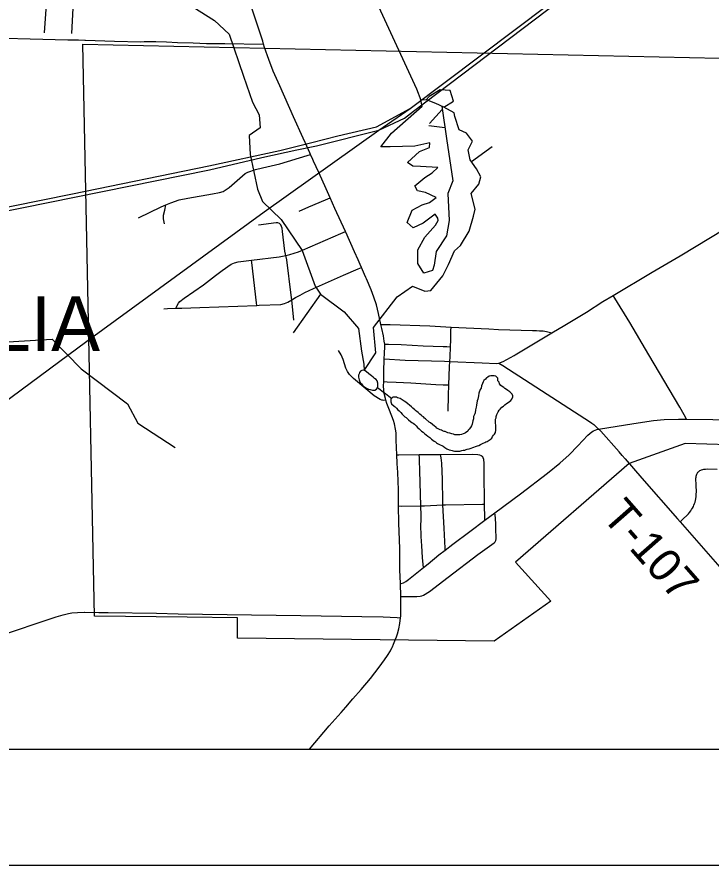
# Model space of a CAD drawing. Extents: x 0 to 34, y 0 to 22.
# Drawn here: x 6.712 to 7.312, y 14 to 14.733 of the extents above; entities that cross this region are included whole.
import ezdxf

# ---------------------------------------------------------------- set-up
doc = ezdxf.new("R2010")
doc.units = 0
for name, color, linetype in [('GM_X_City_Street', 7, 'Continuous'), ('GM_X_Corporation', 7, 'Continuous'), ('GM_X_Corporation_Text', 7, 'Continuous'), ('GM_X_County_Road', 7, 'Continuous'), ('GM_X_Minor_Lake', 7, 'Continuous'), ('GM_X_Minor_River', 7, 'Continuous'), ('GM_X_Rail_Line', 7, 'Continuous'), ('GM_X_State_Route', 7, 'Continuous'), ('GM_X_Township_Road', 7, 'Continuous'), ('GM_X_Township_Road_Text', 7, 'Continuous'), ('SH_Data', 7, 'Continuous')]:
    doc.layers.add(name, color=color, linetype=linetype)

msp = doc.modelspace()

# ---------------------------------------------------------------- linework, layer by layer
at = {"layer": 'GM_X_City_Street'}
for points in [[(6.81731, 14.55908), (6.8371, 14.56867), (6.84094, 14.57031), (6.8454, 14.57222), (6.85255, 14.57456), (6.86005, 14.57624), (6.88142, 14.57977), (6.88755, 14.5809), (6.89051, 14.58202), (6.89323, 14.58354), (6.89579, 14.58535), (6.90976, 14.59741), (6.91187, 14.59858), (6.91849, 14.60097), (6.92451, 14.60231), (6.93956, 14.60592), (6.9631, 14.61288), (6.96622, 14.6138)], [(6.95625, 14.56495), (6.96453, 14.56858), (6.97917, 14.57476), (6.983, 14.57648)], [(6.83993, 14.55384), (6.83914, 14.55836), (6.83917, 14.56132), (6.84006, 14.56581), (6.84094, 14.57031)], [(6.94471, 14.52657), (6.94441, 14.52772), (6.94392, 14.53034), (6.94192, 14.54734), (6.94147, 14.55024), (6.94108, 14.55171), (6.94038, 14.55308), (6.9393, 14.55415), (6.93791, 14.55477), (6.93639, 14.55477), (6.92117, 14.55279)], [(6.84965, 14.48105), (6.85058, 14.48277), (6.85209, 14.48555), (6.85315, 14.48677), (6.85681, 14.48975), (6.87359, 14.50124), (6.88411, 14.50936), (6.88964, 14.5137), (6.89748, 14.519), (6.90036, 14.52037), (6.90346, 14.52112), (6.91507, 14.52254), (6.93898, 14.52547), (6.94471, 14.52657), (6.94828, 14.52747), (6.95583, 14.52988), (6.95928, 14.5312), (6.99244, 14.54572), (6.99645, 14.54748)], [(6.91982, 14.48351), (6.91955, 14.48577), (6.91531, 14.52051), (6.91507, 14.52254)], [(6.9517, 14.47073), (6.94986, 14.48837), (6.94945, 14.4923), (6.94566, 14.5229), (6.94508, 14.52539), (6.94471, 14.52657)], [(6.83946, 14.4806), (6.84254, 14.48084), (6.84965, 14.48105), (6.85492, 14.4812), (6.87048, 14.4818), (6.91982, 14.48351), (6.92175, 14.48357), (6.94042, 14.48439), (6.94356, 14.485), (6.94651, 14.48624), (6.94986, 14.48837), (6.95312, 14.49045), (6.95702, 14.49242), (6.96133, 14.49457), (6.96882, 14.49808), (6.99464, 14.50966), (7.00721, 14.51512), (7.01008, 14.51636)], [(7.29116, 14.38519), (7.2891, 14.38893), (7.28537, 14.39568), (7.25852, 14.44082), (7.24219, 14.46878), (7.22907, 14.48973), (7.22762, 14.49203)], [(7.02683, 14.46707), (7.0302, 14.46698), (7.03488, 14.46686), (7.06911, 14.46587), (7.08762, 14.46466), (7.12016, 14.46314), (7.12862, 14.46275), (7.15795, 14.4618), (7.16149, 14.46175), (7.16411, 14.46165), (7.1671, 14.46142), (7.17005, 14.46082), (7.17479, 14.45986)], [(7.08654, 14.43517), (7.08669, 14.43916), (7.08701, 14.44764), (7.08723, 14.45367), (7.08751, 14.46155), (7.08762, 14.46466)], [(7.0302, 14.45012), (7.03351, 14.45001), (7.04449, 14.44963), (7.06335, 14.44862), (7.08064, 14.4481), (7.08378, 14.44788), (7.08701, 14.44764)], [(7.03127, 14.40149), (7.03081, 14.40152), (7.02953, 14.40137), (7.02839, 14.40152), (7.0276, 14.40173), (7.02632, 14.4023), (7.02121, 14.4055), (7.01391, 14.41133), (7.00319, 14.42036), (6.99993, 14.42379), (6.99809, 14.42638), (6.9967, 14.42924), (6.99433, 14.43666), (6.99253, 14.44072), (6.99027, 14.44458)], [(7.08516, 14.39201), (7.08539, 14.40575), (7.08575, 14.41491), (7.08636, 14.43051), (7.08654, 14.43517)], [(7.02935, 14.4177), (7.03242, 14.41754), (7.04022, 14.41713), (7.05273, 14.41669), (7.0745, 14.41507), (7.08074, 14.41498), (7.08575, 14.41491)], [(7.04374, 14.24309), (7.04456, 14.24328), (7.04652, 14.24374), (7.04853, 14.24501), (7.05087, 14.24662), (7.06385, 14.25709), (7.06773, 14.26022), (7.07708, 14.26793), (7.08255, 14.27217), (7.08897, 14.27715), (7.10366, 14.28827), (7.11687, 14.29803), (7.12548, 14.30439), (7.14765, 14.32078), (7.17103, 14.33849), (7.18167, 14.34725), (7.18968, 14.3545), (7.19727, 14.36224), (7.20566, 14.37136), (7.20925, 14.3744), (7.21056, 14.37522), (7.21349, 14.37629), (7.21511, 14.37655)], [(7.23808, 14.35089), (7.23554, 14.35378), (7.23276, 14.35692), (7.21707, 14.3747), (7.21613, 14.37562), (7.21511, 14.37655)], [(7.04063, 14.35442), (7.04241, 14.35444), (7.05994, 14.3546), (7.07852, 14.35472), (7.10598, 14.3549), (7.11063, 14.35462), (7.11221, 14.35435), (7.11348, 14.35387), (7.11457, 14.35317)], [(7.06385, 14.25709), (7.06355, 14.25951), (7.06277, 14.26561), (7.0624, 14.27586), (7.06176, 14.2839), (7.06156, 14.29412), (7.06172, 14.29745), (7.06159, 14.30209), (7.06136, 14.31035), (7.06053, 14.34054), (7.06036, 14.34985), (7.06023, 14.35139), (7.05994, 14.3546)], [(7.08255, 14.27217), (7.08246, 14.27378), (7.08154, 14.29101), (7.08054, 14.31115), (7.08039, 14.31421), (7.08018, 14.33301), (7.07951, 14.3471), (7.0789, 14.3518), (7.07852, 14.35472)], [(7.11687, 14.29803), (7.11676, 14.30163), (7.11651, 14.30942), (7.11649, 14.31032), (7.11643, 14.31185), (7.11624, 14.33936), (7.11623, 14.34708), (7.11591, 14.35025), (7.11545, 14.35179), (7.1149, 14.35265), (7.11457, 14.35317)], [(7.04216, 14.31019), (7.04442, 14.31018), (7.06136, 14.31035), (7.06295, 14.31032), (7.06451, 14.31029), (7.08054, 14.31115), (7.08272, 14.31119), (7.11481, 14.31182), (7.11643, 14.31185)], [(7.04405, 14.23186), (7.04702, 14.23204), (7.04856, 14.23214), (7.05787, 14.23208), (7.06096, 14.23227), (7.06244, 14.23266), (7.06384, 14.23325), (7.06905, 14.23646), (7.08496, 14.24866), (7.11082, 14.26836), (7.12473, 14.27823), (7.12578, 14.27936), (7.12637, 14.28036), (7.12658, 14.28176), (7.12652, 14.28439), (7.12638, 14.28831), (7.12632, 14.29386), (7.12608, 14.30005), (7.12548, 14.30439)]]:
    msp.add_lwpolyline(points, dxfattribs=at)
at = {"layer": 'GM_X_Corporation'}
msp.add_lwpolyline([(6.7693, 14.70911), (7.34604, 14.69664), (7.34606, 14.56029), (7.34608, 14.36247), (7.29001, 14.36406), (7.24163, 14.34695), (7.14334, 14.26178), (7.17374, 14.22784), (7.12479, 14.19331), (6.90309, 14.19603), (6.90294, 14.21358), (6.85937, 14.21402), (6.77953, 14.215), (6.7728, 14.54029)], close=True, dxfattribs=at)
for points in [[(6.0392, 14.6694), (6.04124, 14.60572), (6.04279, 14.55293), (6.04563, 14.45974), (6.04662, 14.41624), (6.04684, 14.41003), (6.04687, 14.40695), (6.04749, 14.3899), (6.04788, 14.37904), (6.05092, 14.27972), (6.05218, 14.24245), (6.05455, 14.1679), (6.05638, 14.11355), (6.05687, 14.1), (8.9, 14.1)], [(6.0392, 14.6694), (6.04124, 14.60572), (6.04279, 14.55293), (6.04563, 14.45974), (6.04662, 14.41624), (6.04684, 14.41003), (6.04687, 14.40695), (6.04749, 14.3899), (6.04788, 14.37904), (6.05092, 14.27972), (6.05218, 14.24245), (6.05455, 14.1679), (6.05638, 14.11355), (6.05687, 14.1), (8.65472, 14.1)]]:
    msp.add_lwpolyline(points, dxfattribs=at)
at = {"layer": 'GM_X_County_Road'}
for points in [[(7.12893, 14.4337), (7.13224, 14.43156), (7.18449, 14.39783), (7.20812, 14.38254), (7.20913, 14.38185), (7.21097, 14.38051), (7.21276, 14.37886), (7.21511, 14.37655)], [(7.21511, 14.37655), (7.24563, 14.38154), (7.26252, 14.38407), (7.27181, 14.38498), (7.28425, 14.38531), (7.29116, 14.38519)], [(7.29116, 14.38519), (7.31375, 14.38481), (7.34655, 14.38368)]]:
    msp.add_lwpolyline(points, dxfattribs=at)
at = {"layer": 'GM_X_Minor_Lake'}
for points in [[(7.01433, 14.42634), (7.01281, 14.42711), (7.01148, 14.4275), (7.01034, 14.42713), (7.00939, 14.42676), (7.00843, 14.42563), (7.00804, 14.42449), (7.00765, 14.42316), (7.00763, 14.42145), (7.00782, 14.4203), (7.00819, 14.41916), (7.00856, 14.41821), (7.00912, 14.41687), (7.01006, 14.41572), (7.01138, 14.414), (7.01271, 14.41304), (7.01384, 14.41227), (7.01498, 14.41169)], [(7.01433, 14.42634), (7.01281, 14.42711), (7.01148, 14.4275), (7.01034, 14.42713), (7.00939, 14.42676), (7.00843, 14.42563), (7.00804, 14.42449), (7.00765, 14.42316), (7.00763, 14.42145), (7.00782, 14.4203), (7.00819, 14.41916), (7.00856, 14.41821), (7.00912, 14.41687), (7.01006, 14.41572), (7.01138, 14.414), (7.01271, 14.41304), (7.01384, 14.41227), (7.01498, 14.41169), (7.01631, 14.41111), (7.01764, 14.41072), (7.01953, 14.41033), (7.02087, 14.41032), (7.02182, 14.41031), (7.02315, 14.41106), (7.02392, 14.41238), (7.02432, 14.41371), (7.02432, 14.41466), (7.02434, 14.41638), (7.02359, 14.41828), (7.02284, 14.41943), (7.02151, 14.42039), (7.02019, 14.42135), (7.01886, 14.4225), (7.01773, 14.42346), (7.01659, 14.42423), (7.01433, 14.42634)], [(7.01498, 14.41169), (7.01631, 14.41111), (7.01764, 14.41072), (7.01953, 14.41033), (7.02087, 14.41032), (7.02182, 14.41031), (7.02315, 14.41106), (7.02392, 14.41238), (7.02432, 14.41371), (7.02432, 14.41466), (7.02434, 14.41638), (7.02359, 14.41828), (7.02284, 14.41943), (7.02151, 14.42039), (7.02019, 14.42135), (7.01886, 14.4225), (7.01773, 14.42346), (7.01659, 14.42423), (7.01433, 14.42634)], [(7.14006, 14.40237), (7.14103, 14.40445), (7.14085, 14.40541), (7.14029, 14.40674), (7.13934, 14.40808), (7.1384, 14.40885), (7.13745, 14.40943), (7.13651, 14.41), (7.13537, 14.41077), (7.13405, 14.41173), (7.1331, 14.4125), (7.13178, 14.41346), (7.13045, 14.41442), (7.12951, 14.41576), (7.12914, 14.4171), (7.12801, 14.41844), (7.12803, 14.42072), (7.12614, 14.42245), (7.12481, 14.42264), (7.12348, 14.42266), (7.12196, 14.42267), (7.12062, 14.4223), (7.11928, 14.42155), (7.11814, 14.42079), (7.11737, 14.41966), (7.11603, 14.41853), (7.11526, 14.41739), (7.11468, 14.41607), (7.1139, 14.41398), (7.11351, 14.41208), (7.11274, 14.41075), (7.11157, 14.40772), (7.11117, 14.40525), (7.11077, 14.40259), (7.11019, 14.40108), (7.10959, 14.39728), (7.1092, 14.39557), (7.1088, 14.39329), (7.1084, 14.39063), (7.10802, 14.38968), (7.10705, 14.3876), (7.10684, 14.38551), (7.10626, 14.3838), (7.10567, 14.38095), (7.10509, 14.37943), (7.10431, 14.37792), (7.10335, 14.37659), (7.1024, 14.37584), (7.10201, 14.37489), (7.10009, 14.37339), (7.09895, 14.37282), (7.098, 14.37245), (7.09647, 14.37208), (7.09514, 14.37171), (7.094, 14.37153), (7.09266, 14.37154), (7.09171, 14.37155), (7.09076, 14.37175), (7.08962, 14.37213), (7.08811, 14.37253), (7.0864, 14.37311), (7.08488, 14.3735), (7.08374, 14.37408), (7.08261, 14.37447), (7.08166, 14.37467), (7.08014, 14.37525), (7.07919, 14.37564), (7.07824, 14.37602), (7.07654, 14.37699), (7.0754, 14.37757), (7.07427, 14.37853), (7.07332, 14.3793), (7.07143, 14.38064), (7.06973, 14.38198), (7.06878, 14.38256), (7.06557, 14.38544), (7.06462, 14.38621), (7.06368, 14.38717), (7.06273, 14.38793), (7.06179, 14.3887), (7.06047, 14.38966), (7.05914, 14.391), (7.05801, 14.39177), (7.05706, 14.39254), (7.05612, 14.39331), (7.05461, 14.39465), (7.05328, 14.3958), (7.05158, 14.39734), (7.05007, 14.39849), (7.04837, 14.39984), (7.04704, 14.4008), (7.04534, 14.40195), (7.04439, 14.40253), (7.04345, 14.40311), (7.0425, 14.40349), (7.04136, 14.40369), (7.04041, 14.40408), (7.03889, 14.40428), (7.03737, 14.40429), (7.03618, 14.40312)], [(7.03618, 14.40312), (7.03564, 14.4026), (7.03544, 14.40108), (7.03561, 14.40021), (7.03599, 14.39841), (7.03826, 14.39649), (7.03921, 14.39572), (7.04034, 14.39457), (7.04166, 14.39323), (7.0428, 14.39227), (7.04412, 14.39093), (7.04544, 14.38959), (7.04657, 14.38825), (7.0477, 14.38729), (7.04865, 14.38652), (7.04997, 14.38556), (7.05092, 14.3846), (7.05262, 14.38307), (7.05375, 14.3823), (7.0547, 14.38172), (7.05583, 14.38076), (7.05734, 14.37942), (7.05867, 14.37808), (7.05999, 14.37693), (7.06112, 14.37577), (7.06207, 14.37482), (7.06358, 14.37404), (7.06471, 14.37289), (7.06604, 14.37174), (7.06755, 14.37059), (7.06925, 14.36925), (7.07076, 14.3679), (7.0719, 14.36694), (7.07284, 14.36618), (7.07398, 14.3656), (7.07492, 14.36483), (7.07587, 14.36425), (7.07814, 14.3629), (7.07966, 14.36232), (7.08061, 14.36174), (7.08231, 14.36059), (7.08402, 14.35962), (7.08591, 14.35885), (7.08724, 14.35846), (7.08838, 14.35807), (7.08952, 14.35787), (7.09066, 14.35767), (7.09199, 14.35747), (7.09313, 14.35746), (7.09408, 14.35746), (7.09522, 14.35764), (7.09694, 14.358), (7.09808, 14.35838), (7.09941, 14.35856), (7.10056, 14.35893), (7.10151, 14.3593), (7.10323, 14.35967), (7.10494, 14.36023), (7.10628, 14.3606), (7.10723, 14.36097), (7.10876, 14.36153), (7.11028, 14.36209), (7.11162, 14.36246), (7.11295, 14.36321), (7.1141, 14.36377), (7.11524, 14.36433), (7.11677, 14.36508), (7.11773, 14.36564), (7.11868, 14.36602), (7.12136, 14.36771), (7.1227, 14.36884), (7.12347, 14.37016), (7.12423, 14.3713), (7.125, 14.37224), (7.12596, 14.37357), (7.12636, 14.37566), (7.12637, 14.37661), (7.12637, 14.37756), (7.12639, 14.37908), (7.1262, 14.38003), (7.12603, 14.38175), (7.12603, 14.38308), (7.12604, 14.38403), (7.12605, 14.38517), (7.12644, 14.38631), (7.12645, 14.38764), (7.12703, 14.38916), (7.12761, 14.39029), (7.12838, 14.39162), (7.12915, 14.39294), (7.12992, 14.39389), (7.13145, 14.39559), (7.13279, 14.39653), (7.13413, 14.39766), (7.13547, 14.3986), (7.137, 14.39954), (7.13929, 14.40123), (7.14006, 14.40237)]]:
    msp.add_lwpolyline(points, dxfattribs=at)
at = {"layer": 'GM_X_Minor_River'}
for points in [[(6.96298, 14.87618), (7.0578, 14.67059), (7.06134, 14.66086)], [(6.73634, 14.71907), (6.74145, 14.79206), (6.74647, 14.8021), (6.74728, 14.80951)], [(6.75992, 14.71851), (6.76238, 14.76756), (6.76854, 14.77778), (6.76956, 14.78652)], [(6.86451, 14.74148), (6.88307, 14.72974), (6.89572, 14.71785), (6.90819, 14.68143), (6.91602, 14.65912), (6.92164, 14.64824), (6.92251, 14.63701), (6.91295, 14.63023), (6.91397, 14.61387), (6.92021, 14.58377), (6.92451, 14.57328), (6.94075, 14.55775), (6.95881, 14.5308)], [(7.08135, 14.65486), (7.08968, 14.65989), (7.08689, 14.66904), (7.07815, 14.66986), (7.06859, 14.66385), (7.06608, 14.66101)], [(7.01234, 14.42725), (7.02263, 14.44244), (7.02051, 14.46452), (7.04106, 14.49099), (7.05425, 14.50002), (7.06487, 14.49575), (7.07001, 14.49629), (7.08056, 14.50895), (7.08539, 14.5188), (7.09062, 14.53055), (7.09579, 14.53527), (7.1033, 14.54776), (7.10701, 14.56067), (7.10838, 14.56655), (7.10487, 14.58008), (7.11159, 14.58821), (7.11335, 14.59447), (7.10959, 14.60135), (7.10413, 14.60919), (7.10249, 14.61795), (7.10616, 14.62534), (7.10088, 14.63241), (7.09463, 14.63512), (7.09072, 14.64657), (7.09017, 14.6498), (7.08146, 14.65481), (7.07445, 14.65791), (7.06629, 14.66102), (7.06134, 14.66086)], [(7.07945, 14.6557), (7.08354, 14.6276), (7.08916, 14.59104), (7.08471, 14.58005), (7.08587, 14.55683), (7.08349, 14.54373), (7.07463, 14.5301), (7.07303, 14.51832), (7.07147, 14.51358), (7.06403, 14.51136), (7.05896, 14.51976), (7.05886, 14.53156), (7.06503, 14.54235), (7.07404, 14.55293), (7.07636, 14.55672), (7.07618, 14.559), (7.07373, 14.56244), (7.06359, 14.55453), (7.05482, 14.55061), (7.04971, 14.55502), (7.05398, 14.56564), (7.06257, 14.57032), (7.06905, 14.57237), (7.0746, 14.5767), (7.0655, 14.58114), (7.05848, 14.58234), (7.05623, 14.58692), (7.06484, 14.59389), (7.07134, 14.59803), (7.07613, 14.60255), (7.06111, 14.60343), (7.05464, 14.60367), (7.04991, 14.60694), (7.06025, 14.61656), (7.06884, 14.61992), (7.06925, 14.62391), (7.05629, 14.62096), (7.0348, 14.62056), (7.027, 14.62062), (7.03602, 14.63215), (7.06264, 14.65553), (7.06134, 14.66086)], [(7.07987, 14.65283), (7.0688, 14.64065)], [(7.08219, 14.63689), (7.06822, 14.63875)], [(7.10509, 14.60781), (7.12305, 14.62083)], [(6.95881, 14.5308), (6.97018, 14.50009), (6.97469, 14.49321), (6.99512, 14.47784), (7.00757, 14.46367), (7.01009, 14.44406), (7.01209, 14.43282), (7.01234, 14.42725)], [(6.97469, 14.49321), (6.95124, 14.45972)], [(6.60402, 14.446), (6.74274, 14.45428), (6.76785, 14.42879), (6.80794, 14.39844), (6.81695, 14.38163), (6.84913, 14.36066)], [(7.03618, 14.40312), (7.02393, 14.41241)]]:
    msp.add_lwpolyline(points, dxfattribs=at)
at = {"layer": 'GM_X_Rail_Line'}
msp.add_line((7.02524, 14.63495), (7.05235, 14.65372), dxfattribs=at)
for points in [[(7.02524, 14.63495), (7.04728, 14.64538), (7.05504, 14.65131), (7.2329, 14.78614), (7.45402, 14.95299), (7.62987, 15.08397), (7.90392, 15.28739), (8.1825, 15.49291), (8.39874, 15.65453), (8.55126, 15.76844)], [(7.05235, 14.65372), (7.23255, 14.78962), (7.44775, 14.9523), (7.50799, 14.99688), (7.62848, 15.0864), (7.90044, 15.28913), (8.18737, 15.50057), (8.39561, 15.65662), (8.55056, 15.77192)], [(6.04866, 14.43974), (6.33792, 14.49548), (6.6004, 14.54763), (6.76038, 14.57982), (6.87836, 14.60396), (6.93973, 14.61737), (6.96714, 14.62422), (6.98978, 14.62988), (7.02315, 14.63763), (7.05235, 14.65372)], [(6.0488, 14.43506), (6.33852, 14.4922), (6.60099, 14.54435), (6.87866, 14.60068), (6.92409, 14.61131), (6.95441, 14.61781), (6.97131, 14.62124), (7.02524, 14.63495)], [(6.29906, 14.1), (6.44859, 14.21257), (6.77289, 14.45255), (6.9261, 14.56419), (7.02524, 14.63495)]]:
    msp.add_lwpolyline(points, dxfattribs=at)
at = {"layer": 'GM_X_State_Route'}
msp.add_line((7.04405, 14.23186), (7.04374, 14.24309), dxfattribs=at)
for points in [[(6.92556, 14.70908), (6.92481, 14.71188), (6.91446, 14.74278), (6.91072, 14.75459), (6.90198, 14.78443), (6.892, 14.8155), (6.88732, 14.83029), (6.87796, 14.8599), (6.86959, 14.88656), (6.85179, 14.94282), (6.83826, 14.98577), (6.82745, 15.01981), (6.8269, 15.02158)], [(6.96174, 14.62377), (6.96153, 14.62424), (6.95984, 14.628), (6.95148, 14.64633), (6.93945, 14.67313), (6.93396, 14.68582), (6.92998, 14.69589), (6.92631, 14.70635), (6.92556, 14.70908)], [(7.02977, 14.43734), (7.03006, 14.44187), (7.03038, 14.44808), (7.03026, 14.44966), (7.0302, 14.45012), (7.02988, 14.45273), (7.02914, 14.45734), (7.02779, 14.4635), (7.02683, 14.46707), (7.02485, 14.47645), (7.02306, 14.48388), (7.02086, 14.49048), (7.01851, 14.49681), (7.01449, 14.50631), (7.01403, 14.5076), (7.01278, 14.5103), (7.01008, 14.51636), (7.00905, 14.51869), (7.00732, 14.52289), (7.00412, 14.52985), (6.99673, 14.54688), (6.99645, 14.54748), (6.98708, 14.56728), (6.983, 14.57648), (6.97955, 14.58426), (6.97317, 14.5984), (6.9686, 14.60819), (6.96804, 14.60965), (6.96622, 14.6138), (6.96556, 14.61531), (6.96174, 14.62377)], [(7.14291, 14.44071), (7.17479, 14.45986), (7.18595, 14.46656), (7.20456, 14.47771), (7.21884, 14.48679), (7.22762, 14.49203), (7.26151, 14.51224), (7.28557, 14.52646), (7.32413, 14.54976), (7.33105, 14.55336), (7.33684, 14.55572), (7.3416, 14.55721)], [(7.02935, 14.4177), (7.02956, 14.42601), (7.02977, 14.43734)], [(7.02977, 14.43734), (7.04787, 14.43616), (7.082, 14.43538), (7.08654, 14.43517), (7.11456, 14.43383), (7.12693, 14.43341), (7.12893, 14.4337), (7.1327, 14.4349), (7.14206, 14.4402), (7.14291, 14.44071)], [(7.03127, 14.40149), (7.03079, 14.40302), (7.02981, 14.40752), (7.0294, 14.41056), (7.02924, 14.41361), (7.02935, 14.4177)], [(7.04063, 14.35442), (7.04026, 14.3672), (7.04, 14.37344), (7.03961, 14.37655), (7.03864, 14.38114), (7.03774, 14.38414), (7.03436, 14.39284), (7.03218, 14.39862), (7.03127, 14.40149)], [(7.04216, 14.31019), (7.04209, 14.31379), (7.04216, 14.31835), (7.04202, 14.32216), (7.04185, 14.33358), (7.04168, 14.33725), (7.04165, 14.33793), (7.04157, 14.33958), (7.04121, 14.34255), (7.04085, 14.34708), (7.04063, 14.35442)], [(7.04374, 14.24309), (7.0434, 14.25517), (7.04338, 14.25943), (7.04339, 14.26442), (7.04339, 14.27017), (7.04321, 14.27521), (7.04303, 14.27883), (7.04294, 14.28096), (7.0425, 14.29537), (7.04216, 14.31019)], [(7.04393, 14.2137), (7.04411, 14.21496), (7.04427, 14.21809), (7.04409, 14.23049), (7.04405, 14.23186)], [(6.41731, 14.1), (6.43439, 14.10786), (6.44294, 14.11161), (6.45306, 14.11567), (6.46473, 14.12001), (6.48685, 14.12746), (6.51778, 14.13781), (6.55315, 14.14972), (6.58706, 14.16111), (6.63867, 14.17838), (6.70499, 14.2007), (6.73597, 14.211), (6.74631, 14.21445), (6.75229, 14.21624), (6.75685, 14.21733), (6.75995, 14.21783), (6.76463, 14.21823), (6.77035, 14.21834)], [(6.77035, 14.21834), (6.77087, 14.21836), (6.78305, 14.2182)], [(6.78305, 14.2182), (6.79109, 14.2181), (6.83307, 14.21746), (6.85171, 14.21716), (6.91514, 14.21607)], [(6.91514, 14.21607), (6.95771, 14.21555), (7.01034, 14.21472), (7.02875, 14.2145), (7.04112, 14.21385), (7.04393, 14.2137)], [(7.04032, 14.19722), (7.04117, 14.19968), (7.04238, 14.2042), (7.04326, 14.20879), (7.04393, 14.2137)], [(7.03671, 14.18821), (7.03693, 14.18865), (7.03794, 14.1909), (7.03965, 14.19525), (7.04032, 14.19722)], [(6.9965, 14.13637), (7.00267, 14.1436), (7.00986, 14.15171), (7.01793, 14.16116), (7.02555, 14.17095), (7.03016, 14.17721), (7.03276, 14.18111), (7.03517, 14.18513), (7.03671, 14.18821)], [(6.96495, 14.1), (6.96512, 14.10019), (6.98236, 14.12017), (6.99261, 14.1318), (6.9965, 14.13637)]]:
    msp.add_lwpolyline(points, dxfattribs=at)
at = {"layer": 'GM_X_Township_Road'}
msp.add_line((7.28544, 14.29657), (7.32196, 14.25491), dxfattribs=at)
for points in [[(6.32207, 14.72482), (6.32356, 14.72482), (6.35151, 14.72392), (6.41831, 14.72222), (6.46646, 14.72075), (6.48665, 14.72038), (6.50372, 14.71957), (6.52236, 14.71915), (6.54412, 14.71872), (6.59038, 14.71728), (6.60126, 14.71723), (6.61056, 14.71702), (6.66026, 14.71563), (6.68045, 14.71496), (6.72395, 14.7138), (6.75626, 14.71303), (6.76546, 14.71289), (6.7711, 14.71271)], [(6.7711, 14.71271), (6.77161, 14.71269), (6.79675, 14.7119), (6.8194, 14.71133), (6.82232, 14.71135), (6.83246, 14.71135), (6.84177, 14.71106), (6.85125, 14.71063), (6.86456, 14.71021), (6.87631, 14.70978), (6.88726, 14.70966), (6.89191, 14.70964), (6.92507, 14.70908), (6.92556, 14.70908)], [(7.23808, 14.35089), (7.25255, 14.33418), (7.28328, 14.29902), (7.28544, 14.29657)], [(7.28544, 14.29657), (7.28849, 14.2994), (7.29143, 14.30211), (7.29269, 14.30343), (7.29376, 14.30466), (7.29465, 14.30589), (7.29546, 14.3071), (7.29622, 14.3083), (7.29695, 14.30965), (7.29751, 14.31099), (7.29797, 14.31231), (7.2984, 14.31356), (7.29872, 14.31495), (7.29902, 14.31648), (7.29928, 14.31827), (7.29952, 14.3204), (7.29957, 14.32257), (7.29953, 14.32783), (7.29923, 14.33437), (7.29926, 14.33519), (7.29936, 14.33599), (7.29958, 14.33686), (7.29984, 14.33759), (7.30014, 14.33818), (7.30049, 14.33875), (7.3009, 14.33928), (7.30134, 14.33977), (7.30197, 14.34029), (7.30264, 14.34079), (7.30339, 14.3412), (7.30412, 14.34151), (7.30503, 14.3418), (7.30601, 14.34201), (7.30745, 14.34215), (7.30886, 14.34223), (7.3176, 14.34208)]]:
    msp.add_lwpolyline(points, dxfattribs=at)
at = {"layer": 'SH_Data'}
for p, q in [((2.1, 14.1), (8.9, 14.1)), ((2.1, 14.1), (8.9, 14.1)), ((2, 14), (9, 14)), ((2, 14), (9, 14))]:
    msp.add_line(p, q, dxfattribs=at)

# ---------------------------------------------------------------- texts
at = {"layer": 'GM_X_Corporation_Text'}
msp.add_text('CASTALIA', height=0.047348, rotation=0.00001, dxfattribs=at).set_placement((6.47805, 14.44412))
at = {"layer": 'GM_X_Township_Road_Text'}
msp.add_text('T-107', height=0.028409, rotation=311.23836, dxfattribs=at).set_placement((7.21703, 14.30053))

doc.saveas('drawing.dxf')
